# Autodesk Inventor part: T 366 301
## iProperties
Created: 2005-10
Part Number: T 366 301
Material: Stahl (schweißbar)
Description: Schaltrohr
Vendor: Autodesk Inc.
Document SubType Name: Modeling
Standard: DIN59410
Designer: I.Baliuc
Size Designation: 120 x 60 x 6.3 - 400
Density: 7.86 g/cm^3
Zweck: Trenner HSE/HSD 3-polig
Rohabmessung: Rechteckrohr 120 x 60 x 6.3 - 400
Author: T.Messerschmitt
Revision Number: 366301
Comments: Hohlprofil DIN59410 - 120 x 60 x 6.3 - 400 Trenner HSE/HSD 3-polig
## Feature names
1. Körper [Extrusion]
2. Rundung1 [Fillet]
3. Rundung2 [Fillet]
4. Bohrung1 [Hole]
5. Bohrung2 [Hole]
6. Rechteckige Anordnung1 [Rectangular Pattern]
7. Extrusion2
